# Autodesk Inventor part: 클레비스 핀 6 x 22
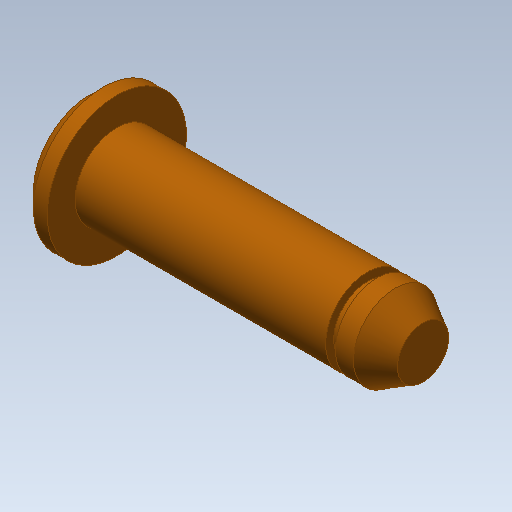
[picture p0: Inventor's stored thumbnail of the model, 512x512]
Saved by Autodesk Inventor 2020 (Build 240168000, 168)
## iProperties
Created: 2017-08
Part Number: 클레비스 핀 6 x 22
Material: 강철
Description: 머리가 있는 클레비스 핀
Document SubType Name: Modeling
Standard: ISO 2341
Designer: mduedu
Standard Revision: Second edition 1986-11-01
Standards Organization: ISO
Language: ko-KR
Size Designation: B - 6 x 24
Categories: <MemberInstance><Categories><Category DisplayName="조임쇠" InternalName="e4da775c-781d-43d5-af7c-5136215cf5a6" Mnemonic="FSTN"><Category DisplayName="핀" InternalNa
Density: 7.85 g/cm^3
Appearance: 주황색
IsCustomPart: 1
Author: mduedu
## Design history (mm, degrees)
sketch "스케치1"
  geometry: L1 (-2, 0)-(-2, 5); L2 (-2, 5)-(0, 5); L3 (0, 5)-(0, 3); L4 (0, 3)-(22, 3); L5 (22, 3)-(22, 0); L6 (-2, 0)-(22, 0); L7 (-7, 0)-(28, 0) reference; L8 (0, -1.96)-(0, 6.16) reference; C1 r 0.8 at (18.8, 0)
  constraints: 12 end point, 3 parallel, 2 collinear, 2 perpendicular, 1 centre point, 1 point on line, 1 vertical
  dimensions: "d0" = 6 diameter of L4 L6 (= NND); "d1" = 10 diameter of L2 L6 (= KOD); "d2" = 2 distance of L1.end L2.end (= KOH); "d3" = 22 distance of L3.end L4.end (= NLG); "d5" = 3.2 distance from line of L5 C1.centre (= DIST); "d6" = 1.6 diameter of C1 (= BOR)
revolve "본체" stored, may be unused: angle "d4" = 90 deg
workplane "Work Plane1"
node "작업 평면4"
sketch "스케치2"
  geometry: C1 r 3 at (0, 0) reference; C2 r 2.425 at (0, 0); 1 further point
  constraints: 1 centre point, 1 coincident
  dimensions: "d33" = 4.85 diameter of C2
extrude "돌출2" cut sketch "스케치2" distance "d34" = 0.7; taper "d35" = 0 deg
body "Solid1"
chamfer "모따기1" distance "d9" = 1 (= PHH2); stored, may be unused: angle "d10" = 45 deg (= FAWI2), second distance "d16" = 1 (= PHH2)
chamfer "모따기2" distance "d11" = 2 (= PHH1); stored, may be unused: angle "d12" = 30 deg (= FAWI1), second distance "d17" = 2 (= PHH1)
other parameters: "PHH1" = 2 [user parameter; used in 2 equation terms], "PHH2" = 1 [user parameter; used in 2 equation terms], "KOD" = 10 [user parameter; used in 1 equation term], "KOH" = 2 [user parameter; used in 1 equation term], "NND" = 6 [user parameter; used in 1 equation term], "FAWI1" = 30 deg [user parameter; used in 1 equation term], "FAWI2" = 45 deg [user parameter; used in 1 equation term], "DIST" = 3.2 [user parameter; used in 1 equation term], "BOR" = 1.6 [user parameter; used in 1 equation term], "NLG" = 22 [user parameter; used in 1 equation term], "d13" = 0, "d14" = 0, "d30" = 0, "d32" = 18
